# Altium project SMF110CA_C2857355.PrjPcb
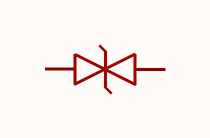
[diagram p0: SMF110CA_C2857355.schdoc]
1 sheet, 1 parts. Net scope: global (net labels, ports and power ports of the same name join across sheets).

## Sheet SMF110CA_C2857355.schdoc
size 127 x 101 mm

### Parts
D?  smf110ca_c2857355  [SOD-123FL_L2.8-W1.8-LS3.7-BI]  (value not drawn)

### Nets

Not connected (* = marked no-connect by the designer): D? 1 2

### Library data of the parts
D? = smf110ca_c2857355: 极性:双向;反向截止电压(Vrwm):110V;钳位电压:177V;峰值脉冲电流(Ipp):1.1A;峰值脉冲功率(Ppp):200W@10/1000us;击穿电压(VBR):122V;; Manufacturer: JSMSEMI(杰盛微); AddInBom: yes; ModelId: d105299b3871451c86f679efef28ff8f; ModelTransform: 145.669,70.866,0,0,0,0,0,0,0; Polarity: 双向; Reverse Stand-Off Voltage (Vrwm): 110V; Clamping Voltage: 177V; Peak Pulse Current (Ipp): 1.1A; Voltage - Breakdown: 122V; Reverse Leakage Current (Ir): 1uA; Number of Channels: 单路; Type: TVS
